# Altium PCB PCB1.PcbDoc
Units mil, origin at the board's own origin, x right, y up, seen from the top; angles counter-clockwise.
Board outline 6000 x 4000 mil, 2 copper layers (Top Layer, Bottom Layer); 60 components, 51 nets, 224 pads, 9 vias.
Unrouted connection lines stored in the file: 119.
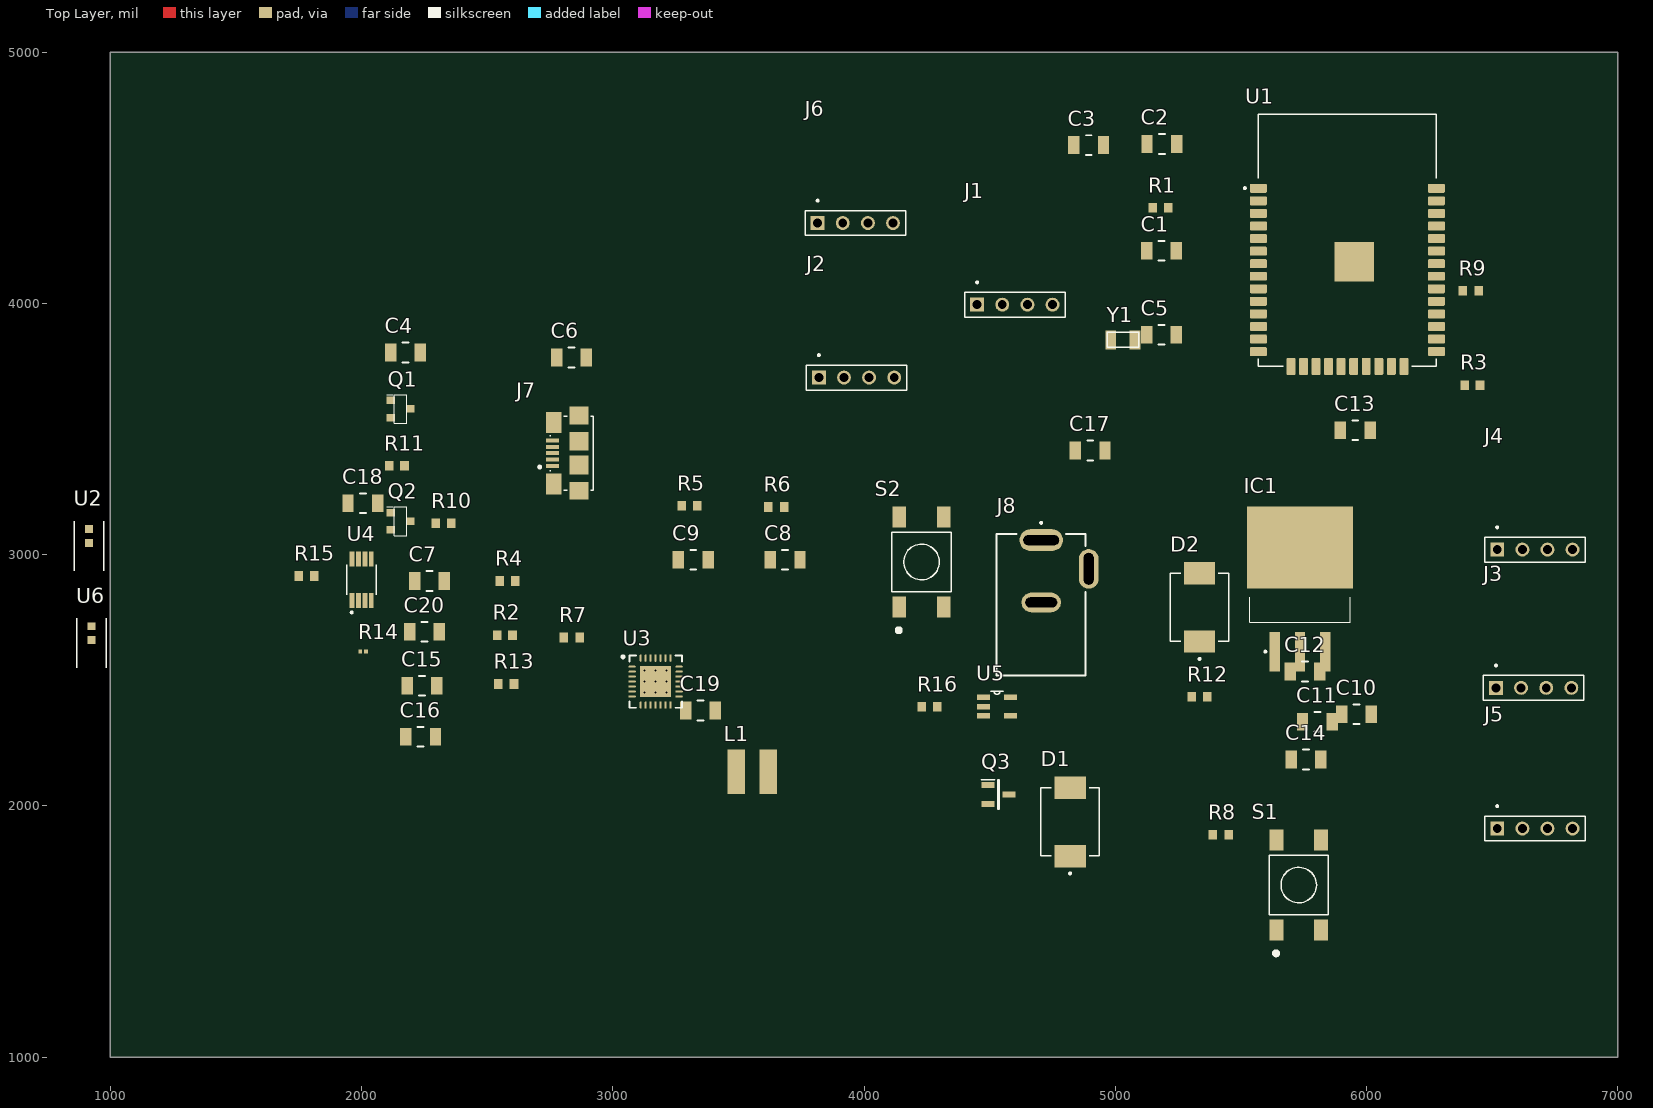
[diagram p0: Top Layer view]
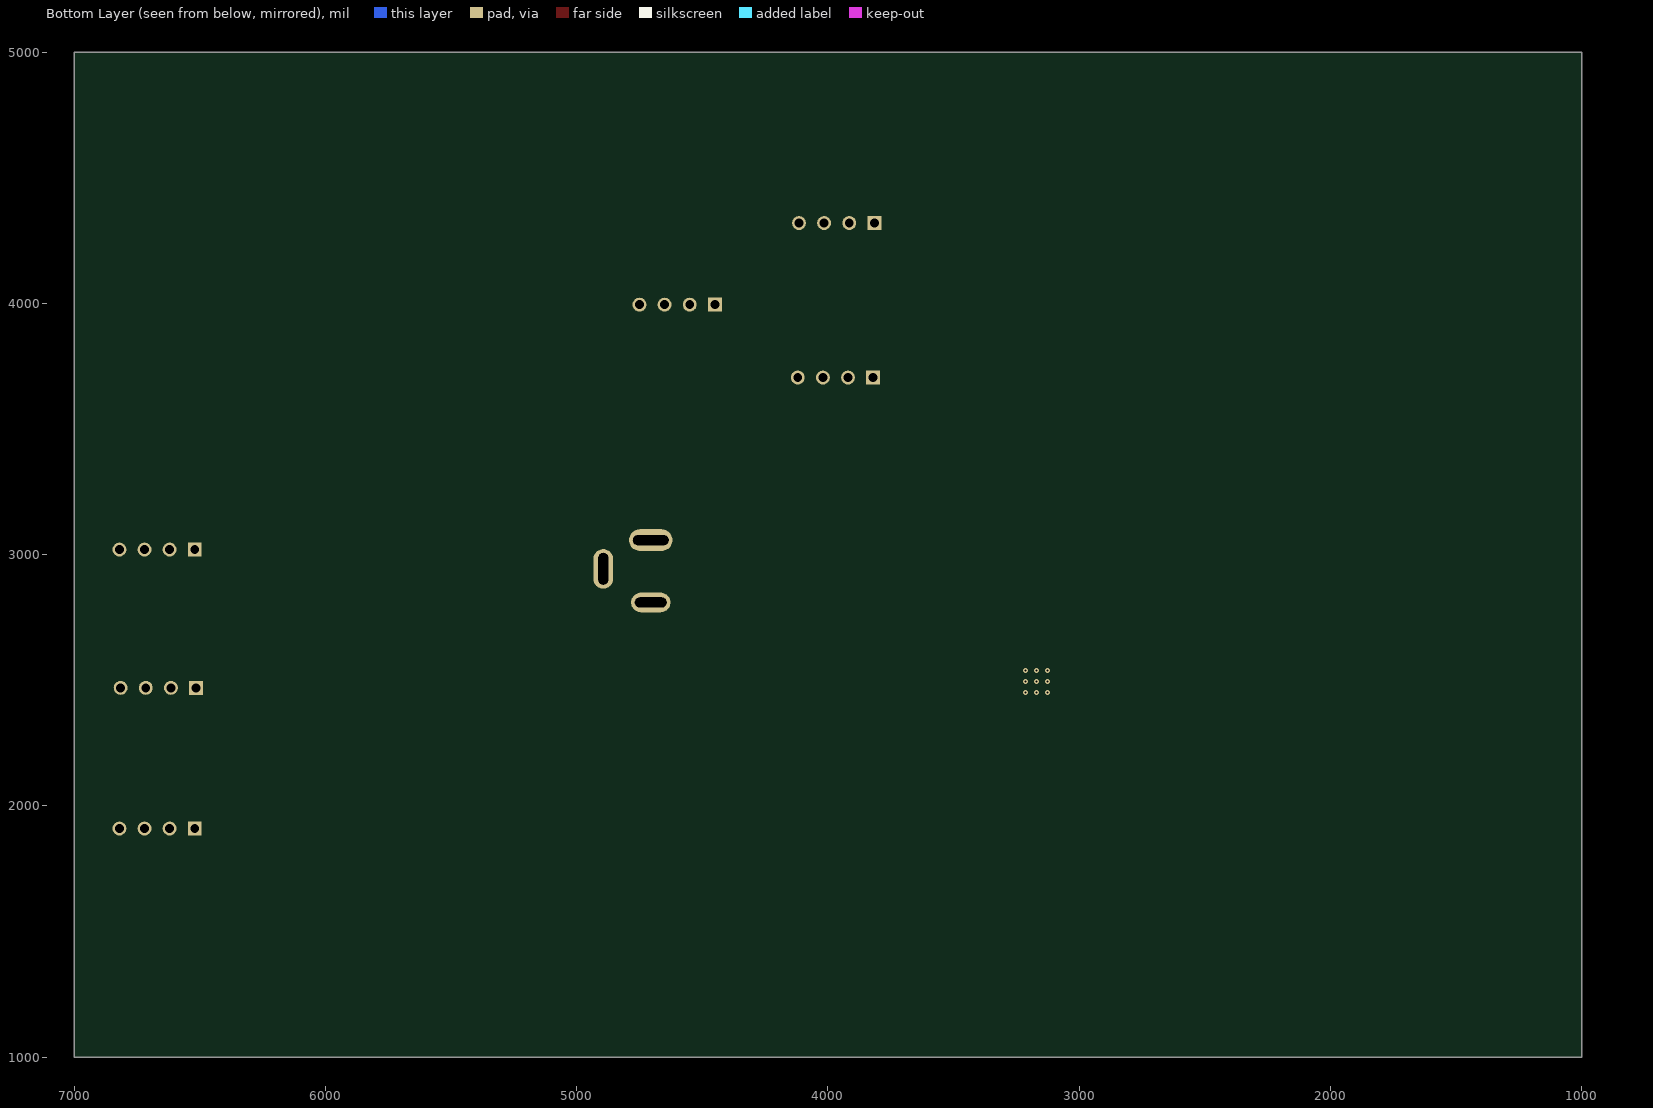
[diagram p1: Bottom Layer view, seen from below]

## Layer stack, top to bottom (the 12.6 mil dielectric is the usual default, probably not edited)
Top Solder: solder mask 0.4, Solder Resist, Dk 3.5
Top Layer: signal copper 1.4
Dielectric 1: dielectric 12.6, FR-4, Dk 4.8
Bottom Layer: signal copper 1.4
Bottom Solder: solder mask 0.4, Solder Resist, Dk 3.5

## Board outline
1000,1000 7000,1000 7000,5000 1000,5000

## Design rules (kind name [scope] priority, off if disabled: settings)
Clearance [All] p1: gap=10 ignorepadtopadclearanceinfootprint=FALSE except(0: Arc-Hole Track-Hole SMDPad-Hole THPad-Hole Via-Hole Fill-Hole Poly-Hole Region-Hole Text-Hole)
PolygonConnect [All] p1: connectstyle=Relief reliefconductorwidth=10 reliefentries=4 polygonreliefangle="90 Angle" airgapwidth=10
RoomDefinition uARM [InComponentClass('uARM')] p1: confinementstyle=ConfineIn formatcopy=TRUE lockcomponents=FALSE outline 160,195 2160,195 2160,1195 160,1195
RoutingVias [All] p1: holewidth=28 width=50 viastyle="Through Hole" minholewidth=28 minwidth=50 maxholewidth=28 maxwidth=50
SolderMaskExpansion [All] p1: expansion=4 istentingtop=FALSE
Width [All] p1: maxlimit=10 minlimit=10 preferedwidth=10
30 further rules are at their usual default settings.

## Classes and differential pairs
component class uARM: C1 C2 C3 C4 C5 C6 C7 C8 C9 C10 C12 C13 C14 C15 C16 C17 C18 C19 C20 D2 IC1 J1 J2 J3 J4 J5 J6 J7 L1 Q1 Q3 R1 R2 R3 R4 R5 R6 R7 R8 R9 R10 R11 R12 R13 R14 R15 R16 S1 S2 U1 U2 U3 U4 U5 U6 Y1

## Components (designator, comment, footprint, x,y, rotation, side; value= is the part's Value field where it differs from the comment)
C1 "C1206C106K3RACTU" C_3216[1206]_N 5184.06,4210 r0 top value=10uF
C2 "C1206C106K3RACTU" C_3216[1206]_N 5185,4635 r0 top value=0.1uF
C3 "C1206C106K3RACTU" C_3216[1206]_N 4894.06,4630 r0 top value=10uF
C4 "C1206C106K3RACTU" C_3216[1206]_N 2175,3805 r0 top value=0.1uF
C5 "C1206C106K3RACTU" C_3216[1206]_N 5184.06,3875 r0 top value=27pF
C6 "C1206C106K3RACTU" C_3216[1206]_N 2835,3785 r0 top value=27pF
C7 "C1206C106K3RACTU" C_3216[1206]_N 2270,2895 r0 top value=0.1uF
C8 "C1206C106K3RACTU" C_3216[1206]_N 3685.94,2980 r0 top value=10uF
C9 "C1206C106K3RACTU" C_3216[1206]_N 3320,2980 r0 top value=1uF
C10 "C1206C106K3RACTU" C_3216[1206]_N 5960,2365 r0 top value=10uF
C11 "C1206C106K3RACTU" C_3216[1206]_N 5804.06,2335 r0 top value=1uF
C12 "C1206C106K3RACTU" C_3216[1206]_N 5755,2535 r0 top value=1uF
C13 "C1206C106K3RACTU" C_3216[1206]_N 5955,3495 r0 top value=1uF
C14 "C1206C106K3RACTU" C_3216[1206]_N 5759.06,2185 r0 top value=1uF
C15 "C1206C106K3RACTU" C_3216[1206]_N 2240,2478.19 r0 top value=10uF
C16 "C1206C106K3RACTU" C_3216[1206]_N 2235,2275 r0 top value=10uF
C17 "C1206C106K3RACTU" C_3216[1206]_N 4900,3415 r0 top value=0.1uF
C18 "C1206C106K3RACTU" C_3216[1206]_N 2005,3205 r0 top value=0.1uF
C19 "C1206C106K3RACTU" C_3216[1206]_N 3349.06,2380 r0 top value=10uF
C20 "C1206C106K3RACTU" C_3216[1206]_N 2250,2693.19 r0 top value=10uF
D1 "SS34" DIOM7959X265N 4820,1936.02 r90 top
D2 "SS34" DIOM7959X265N 5335,2790 r90 top
IC1 "TC1264-3.3VEBTR" TC126433VEBTR 5735,2850 r0 top
J1 "215297-4" TE_215297-4 4600,3995 r0 top
J2 "215297-4" TE_215297-4 3970,3705 r0 top
J3 "215297-4" TE_215297-4 6665,2470 r0 top
J4 "215297-4" TE_215297-4 6670,3020 r0 top
J5 "215297-4" TE_215297-4 6670,1910 r0 top
J6 "215297-4" TE_215297-4 3965,4320 r0 top
J7 "10118192-0001LF" AMPHENOL_10118192-0001LF 2760,3403.82 r90 top
J8 "DCJ235-05-A-XX-X_REVA" GCT_DCJ235-05-A-XX-X_REVA 4705,2800 r0 top
L1 "744773122" WE-PD2-S 3555,2135 r0 top
Q1 "SS8050-G" MBTB-T-SOT23 2155,3580 r0 top
Q2 "SS8050-G" MBTB-T-SOT23 2155,3133.19 r0 top
Q3 "IRLM6402" SOT95P237X112-3N 4535,2045 r0 top
R1 "CRG0603F10K/10" RESC1608X55N#1 5180,4380 r0 top
R2 "CRG0603F10K/10" RESC1608X55N#1 2570,2680 r0 top
R3 "CRG0603F10K/10" RESC1608X55N#1 6420.71,3675 r0 top
R4 "CRG0603F10K/10" RESC1608X55N#1 2580.71,2895 r0 top
R5 "ERJ-S03F4700V" RESC1608X55N#2 3305,3195 r0 top
R6 "ERJ-S03F4700V" RESC1608X55N#2 3650,3190 r0 top
R7 "ERJ-S03F4700V" RESC1608X55N#2 2836.5,2670 r0 top
R8 "ERJ-S03F4700V" RESC1608X55N#2 5420,1885 r0 top
R9 "ERJ-S03F4700V" RESC1608X55N#2 6415,4050 r0 top
R10 "CRG0603F10K/10" RESC1608X55N#1 2325.71,3125 r0 top
R11 "CRG0603F10K/10" RESC1608X55N#1 2140,3353.19 r0 top
R12 "CRG0603F10K/10" RESC1608X55N#1 5335,2435 r0 top
R13 "ERJ-S03F4700V" RESC1608X55N#2 2575,2485 r0 top
R14 "ERJ-1GEF5232C" RESC0603X26N 2006.06,2615 r0 top
R15 "CRG0603F10K/10" RESC1608X55N#1 1780,2915 r0 top
R16 "CRG0603F10K/10" RESC1608X55N#1 4260,2395 r0 top
S1 "5-1437565-0" SW_5-1437565-0 5730,1685 r90 top
S2 "5-1437565-0" SW_5-1437565-0 4228.58,2970.87 r90 top
U1 "ESP-WROOM-32" MODULE_ESP-WROOM-32 5923.66,4133.19 r0 top
U2 "SPMWHT541MP5WATMS4" LED_SPMWHT541MP5WAPKS4 915,3035 r90 top
U3 "CP2109-A01-GM" SLAB-QFN-28-3125x3125TP_L 3170,2495 r0 top
U4 "MCP16311T-E/MS" SOP65P490X110-8N 2000,2900 r90 top
U5 "MCP601T-E/OT" SOT95P270X145-5N 4529,2395 r0 top
U6 "SPMWHT541MP5WATMS4" LED_SPMWHT541MP5WAPKS4 925,2648.19 r90 top
Y1 "ABS07-32.768KHZ-9-1-T" XTAL320X150X90 5030,3855 r0 top

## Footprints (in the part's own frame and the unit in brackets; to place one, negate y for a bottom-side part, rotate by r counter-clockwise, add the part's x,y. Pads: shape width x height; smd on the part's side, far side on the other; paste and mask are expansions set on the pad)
AMPHENOL_10118192-0001LF [mm]
  rect 0.4x1.35 smd: 1(-1.3,0) 2(-0.65,0) 3(0,0) 4(0.65,0) 5(1.3,0)
  rect 2.1x1.6 smd: SH1(-3.1,-0.125) SH2(3.1,-0.125)
  rect 1.8x1.9 smd: SH3(-3.8,-2.675) SH6(3.8,-2.675)
  rect 1.9x1.9 smd: SH4(-1.2,-2.675) SH5(1.2,-2.675)
  silkscreen extent -3.75,-4.13 3.75,1.4, body extent -3.95,-2.41 3.95,3.21, height 2.7
C_3216[1206]_N [mm]
  rect 1.15x1.8 smd: 1(-1.5,0) 2(1.5,0)
  silkscreen extent -0.3,-1 0.3,1, body extent -1.6,-0.8 1.6,0.8, height 1
DIOM7959X265N [mm]
  rect 2.25x3.18 smd: A(3.455,0) C(-3.455,0)
  silkscreen extent -5.3,-2.95 3.44,2.95, body extent -3.98,-2.95 3.98,2.95, height 1.2
GCT_DCJ235-05-A-XX-X_REVA [mm]
  oval 4.4x2.2 hole 1 slot 3.6 at 0 deg: 1(0,6.55)
  oval 4x2 hole 1 slot 3.2 at 0 deg: 2(0,0.25)
  oval 2x4 hole 1 slot 3.2 at 90 deg: 3(4.8,3.65)
  silkscreen extent -4.5,-7.15 4.5,8.4
LED_SPMWHT541MP5WAPKS4 [mm]
  rect 0.8x0.8 smd paste-1 mask+0: A(1.7,0) C(0.3,0)
  silkscreen extent -2.5,-1.5 2.5,1.5, body extent -2.8,-1.5 2.8,1.5, height 0.8
MBTB-T-SOT23 [mm]
  rect 0.85x0.75 smd: 1(-1,0.875) 2(-1,-0.875) 3(1,0)
  silkscreen extent -1.38,-1.45 0.65,1.45
MODULE_ESP-WROOM-32 [mm]
  rrect22% 1.7x0.9 smd: 1(-9,8.255) 2(-9,6.985) 3(-9,5.715) 4(-9,4.445) 5(-9,3.175) 6(-9,1.905) 7(-9,0.635) 8(-9,-0.635) 9(-9,-1.905) 10(-9,-3.175) 11(-9,-4.445) 12(-9,-5.715) 13(-9,-6.985) 14(-9,-8.255) 25(9,-8.255) 26(9,-6.985) 27(9,-5.715) 28(9,-4.445) 29(9,-3.175) 30(9,-1.905) 31(9,-0.635) 32(9,0.635) 33(9,1.905) 34(9,3.175) 35(9,4.445) 36(9,5.715) 37(9,6.985) 38(9,8.255)
  rect 4x4 smd: 1.1(0.7,0.845)
  rrect22% 0.9x1.7 smd: 15(-5.715,-9.755) 16(-4.445,-9.755) 17(-3.175,-9.755) 18(-1.905,-9.755) 19(-0.635,-9.755) 20(0.635,-9.755) 21(1.905,-9.755) 22(3.175,-9.755) 23(4.445,-9.755) 24(5.715,-9.755)
  silkscreen extent -10.46,-9.75 9,15.75, body extent -9,-12.75 9,12.75, height 3.25
RESC0603X26N [mm]
  rect 0.38x0.4 smd: 1(-0.281,0) 2(0.281,0)
  body extent -0.3,-0.15 0.3,0.15, height 0.26
RESC1608X55N#1 [mm]
  rect 0.87x0.97 smd: 1(-0.78,0) 2(0.78,0)
  body extent -0.8,-0.4 0.8,0.4, height 0.55
RESC1608X55N#2 [mm]
  rect 0.87x0.98 smd: 1(-0.8,0) 2(0.8,0)
  body extent -0.8,-0.4 0.8,0.4, height 0.55
SLAB-QFN-28-3125x3125TP_L [mm] "QFN, 28-Leads, Body 5x5mm, Pitch 0.5mm, Thermal Pad 3.13x3.13mm, IPC High Density"
  oval 0.75x0.2 smd: 1(-2.375,1.5) 2(-2.375,1) 3(-2.375,0.5) 4(-2.375,0) 5(-2.375,-0.5) 6(-2.375,-1) 7(-2.375,-1.5) 15(2.375,-1.5) 16(2.375,-1) 17(2.375,-0.5) 18(2.375,0) 19(2.375,0.5) 20(2.375,1) 21(2.375,1.5)
  oval 0.2x0.75 smd: 8(-1.5,-2.375) 9(-1,-2.375) 10(-0.5,-2.375) 11(0,-2.375) 12(0.5,-2.375) 13(1,-2.375) 14(1.5,-2.375) 22(1.5,2.375) 23(1,2.375) 24(0.5,2.375) 25(0,2.375) 26(-0.5,2.375) 27(-1,2.375) 28(-1.5,2.375)
  rect 3.13x3.13 smd: 29(0,0)
  silkscreen extent -3.42,-2.65 2.65,2.65, body extent -2.5,-2.5 2.5,2.5, height 1
SOP65P490X110-8N [mm]
  rect 1.5x0.49 smd: 1(-2.105,0.975) 2(-2.105,0.325) 3(-2.105,-0.325) 4(-2.105,-0.975) 5(2.105,-0.975) 6(2.105,-0.325) 7(2.105,0.325) 8(2.105,0.975)
  silkscreen extent -3.4,-1.5 1.5,1.5
SOT95P237X112-3N [mm]
  rect 1.3x0.6 smd: 1(-1.05,0.95) 2(-1.05,-0.95) 3(1.05,0)
  silkscreen extent -1.7,-1.46 0.05,1.5, body extent -1.18,-1.46 1.18,1.46, height 1.12
SOT95P270X145-5N [mil]
  rect 52x22 smd: 1(-54,37) 2(-54,0) 3(-54,-37) 4(54,-37) 5(54,37)
  silkscreen extent -25,49 25,61, body extent -57,-53 57,53, height 57
SW_5-1437565-0 [mm]
  rect 2.1x1.4 smd: 1(-4.55,2.25) 2(4.55,2.25) 3(-4.55,-2.25) 4(4.55,-2.25)
  silkscreen extent -7.1,-3 3,3, body extent -3,-5 3,5, height 7.26
TC126433VEBTR [mm]
  rect 1.041x3.988 smd: 1(-2.54,-6.009) 2(0,-6.009) 3(2.54,-6.009)
  rect 10.744x8.306 smd: 4(0,4.545)
  silkscreen extent -5.08,-6.1 5.08,-0.51
TE_215297-4 [mm]
  rect 1.408x1.408 hole 0.9: 1(-3.81,0)
  round 1.408 hole 0.9: 2(-1.27,0) 3(1.27,0) 4(3.81,0)
  silkscreen extent -5.08,-1.26 5.08,2.36, body extent -5.08,0 5.08,10, height 1.26
WE-PD2-S [mm] "SMD Inductor, 2-Leads, Body 4.5 x 4.0 mm"
  rect 1.75x4.5 smd: 1(-1.625,0) 2(1.625,0)
  body extent -2.23,-2 2.23,2, height 3.17
XTAL320X150X90 [mil]
  rect 43x75 smd: 1(-48,0) 2(48,0)
  silkscreen extent -63,-30 63,30, body extent -63,-30 63,30, height 35

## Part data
C1 C2 C3 C4 C5 C6 C7 C8 C9 C10 C11 C12 C13 C14 C15 C16 C17 C18 C19 C20: library part C_10uf_3216[1206], "Capacitor Céramique 10uf XR7 25V 10%", Manufacturer=KEMET, Supplier Part Number 1=399-7442-1-ND
D1 D2: "Diode Schottky 40V 3A 2-Pin SMC T/R", Package=None
IC1: "Integrated Circuit", Manufacturer_Name=Microchip, Mouser Part Number=579-TC1264-3.3VEBTR
J1 J2 J3 J4 J5 J6 R5 R6 R7 R8 R9 R13 U2 U5 U6: Package=None
J7: "Single Port 5 Contact Horizontal Right Angle Shielded Micro B USB 2.0 Connector", Package=None
J8: "DC Power Jack, Thru-Hole, Horizontal, with Locating Pegs, D2.35mm", Package=None
L1: "SMD Power Inductor WE-PD2, L = 22.0 µH", Inductance="22.0 ÂµH"
Q1 Q2: "<b>Bipolar Transistors - BJT NPN TRANSISTOR 1.5A 40V</b><p> Source: <a href=\"https://componentsearchengine.com/Datasheets/1/SS8050-G.pdf\"> Datasheet </a>", Package=None
Q3: "MOSFET (P-Channel)", Manufacturer_Name=Infineon
R1 R2 R3 R4 R10 R11 R12 R15 R16: "Thick Film Resistors - SMD CRG0603 1% 10K 10K RL", Package=None
R14: "Res Thick Film 0201 52.3K Ohm 1% 0.05W(1/20W) Â±200ppm/C SMD T/R", Package=None
S1 S2: "Switch Tactile OFF (ON) Round Button Gull Wing 0.05A 12VDC 1.57N SMD T/R", Package=None
U1: "Module: combo; GPIO, I2C x2, I2S x2, SDIO, SPI x3, UART x3; 19.5dBm", Package=None
U3: "Single-Chip USB to UART Bridge, 1024 Bytes EEPROM, -40 to 85 degC, 28-pin QFN, Tube", Manufacturer="Silicon Labs"
U4: "The MCP16311/2 is a compact, high-efficiency, fixed frequency, synchronous step-down DC-DC converter in an 8-pin MSOP, or 2 x 3 TDFN package that operates from input voltage sources up to 30V. Integrated features include a high-side and a low-side switch, fixed frequency peak current mode control, internal compensation, peak current limit and overtemperature protection. The MCP16311/2 provides all the active functions for local DC-DC conversion, with fast transient response and accurate regulation.", Package=None
Y1: "ABS07 Series 32.768 kHz Â±20 ppm 12.5 pF -40 to +85 C SMT Low Profile Crystal", Package=None

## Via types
v1: diameter 19.68, hole 7.87, Top Layer to Bottom Layer, 9 vias

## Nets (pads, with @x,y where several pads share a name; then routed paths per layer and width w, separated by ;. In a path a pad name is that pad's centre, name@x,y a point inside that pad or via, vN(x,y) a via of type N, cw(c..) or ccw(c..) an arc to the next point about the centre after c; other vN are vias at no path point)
+5: C12.1 C17.2 C19.2 C20.2 D1.C IC1.1 L1.2 Q3.2 R14.2 U5.5
ADC2_0/IO4: U1.26
D+: J7.3 U3.4
D-: J7.2 U3.5
DTR: Q2.3 R10.2 U3.28
EN: C4.2 Q1.2 R4.2 R8.2
GND: C1.1 C2.1 C3.2 C4.1 C5.1 C6.1 C7.1 C8.1 C8.2 C9.1 C9.2 C10.1 C11.1 C12.2 C13.1 C14.2 C15.1 C16.1 C17.1 C19.1 C20.1 D1.A IC1.2 IC1.4 J1.1 J1.4 J2.1 J2.4 J3.1 J3.4 J4.1 J4.4 J5.1 J5.4 J6.1 J6.4 J7.1 J7.5 J8.2 J8.3 Q3.3 R15.1 S1.3 S2.3 U1.1 U1.1.1 U1.15 U1.38 U3.3 U3.8 U3.29 U4.5 U4.8
  other v1: 3126.69,2451.69 3170,2451.69 3213.31,2451.69 3126.69,2495 3170,2495 3213.31,2495 3126.69,2538.31 3170,2538.31 3213.31,2538.31
IO0: Q2.2 R2.2 R3.2 U1.25
IO2/DATA0: R3.1 U1.24
IO5: U1.29
IO12: U1.14
IO13: U1.16
IO14/CLK: U1.13
IO15/CMD: U1.23
IO16/U2RXD: U1.27
IO17/U2TXD: U1.28
IO18: R9.2 U1.30
IO19: U1.31
IO21/SDA: U1.33
IO22/SCL: U1.36
IO23: U1.37
IO25: U1.10
IO26: U1.11
IO27: U1.12
IO34: U1.6
IO35: U1.7
NetC3_1: C3.1 R1.1 U1.3
NetC5_2: C5.2 U1.9
NetC6_2: C6.2 Y1.2
NetC7_2: C7.2 R9.1 S2.1
NetC13_2: C13.2 U4.2
NetC18_1: C18.1 U4.7
NetC18_2: C18.2 L1.1 U4.6
NetD2_A: D2.A J8.1
NetQ1_1: Q1.1 R10.1
NetQ2_1: Q2.1 R11.1
NetQ3_1: Q3.1 U5.1
NetR7_2: R7.2
NetR8_1: R8.1 S1.1
NetR12_2: R12.2 R16.1 U5.3
NetR13_1: R13.1
NetR14_1: R14.1 R15.2 U4.1
NetR16_2: R16.2 U5.2
NetU1_8: U1.8 Y1.1
RTS: Q1.3 R11.2 U3.24
RXD: R5.1 U1.34
RXD_CP2109: R6.2 U3.25
TXD: R6.1 U1.35
TXD_CP2109: R5.2 U3.26
VDD33: C1.2 C2.2 C10.2 C11.2 C14.1 IC1.3 R1.2 R2.1 R4.1 R7.1 R13.2 U1.2 U3.6 U3.7 U5.4
VIN: C15.2 C16.2 D2.C R12.1 U4.3 U4.4
pads on no net: J1.2 J1.3 J2.2 J2.3 J3.2 J3.3 J4.2 J4.3 J5.2 J5.3 J6.2 J6.3 J7.4 J7.SH1 J7.SH2 J7.SH3 J7.SH4 J7.SH5 J7.SH6 S1.2 S1.4 S2.2 S2.4 U1.4 U1.5 U1.17 U1.18 U1.19 U1.20 U1.21 U1.22 U1.32 U2.A U2.C U3.1 U3.2 U3.9 U3.10 U3.11 U3.12 U3.13 U3.14 U3.15 U3.16 U3.17 U3.18 U3.19 U3.20 U3.21 U3.22 U3.23 U3.27 U6.A U6.C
